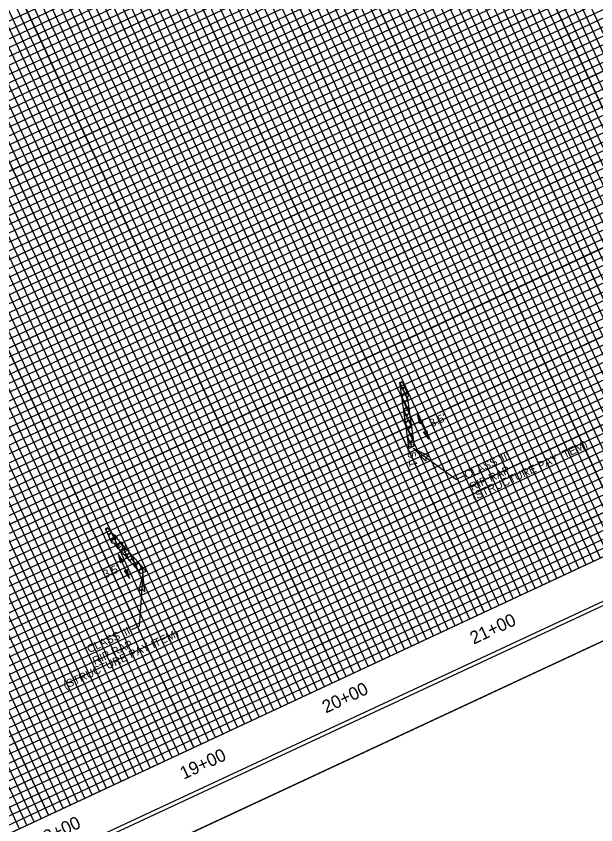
# Model space of a CAD drawing. Extents: x 2320593 to 2322597, y 921119 to 922832.
# Drawn here: x 2321771 to 2322132, y 921501 to 922006 of the extents above; entities that cross this region are included whole.
import ezdxf

# ---------------------------------------------------------------- set-up
doc = ezdxf.new("R2010")
doc.units = 0
for name, color, linetype in [('Default', 7, 'Continuous'), ('Sheet Cutting Line CELL', 7, 'Continuous'), ('Sheet DOT Grid CELL', 7, 'Continuous'), ('Sheet Layout Profile Border Port 2', 7, 'Continuous'), ('Sheet Plan And Profile CELL', 7, 'Continuous'), ('Sheet Plot Border Inside CELL', 7, 'Continuous'), ('Sheet Plot Border Outside CELL', 7, 'Continuous'), ('Sheet Profile Grid Major CELL', 7, 'Continuous'), ('Sheet Profile Grid Middle CELL', 7, 'Continuous'), ('Sheet Profile Grid Minor CELL', 7, 'Continuous')]:
    doc.layers.add(name, color=color, linetype=linetype)

msp = doc.modelspace()

# ---------------------------------------------------------------- linework, layer by layer
at = {"layer": 'Default'}
for p, q in [((2322010.51, 921773.04), (2322011.46, 921773.48)), ((2322011.72, 921764.72), (2322012.58, 921765.12)), ((2322015.98, 921757.82), (2322016.28, 921757.35)), ((2322021.01, 921756.91), (2322028.08, 921741.75)), ((2322012.93, 921756.4), (2322013.7, 921756.76)), ((2322014.15, 921748.09), (2322014.83, 921748.4)), ((2322015.36, 921739.77), (2322015.95, 921740.05)), ((2322019.17, 921737.56), (2322015.9, 921736.03)), ((2322018.23, 921741.11), (2322018.78, 921740.26)), ((2322018.27, 921736.12), (2322045.25, 921716.57)), ((2322049.78, 921718.68), (2322045.25, 921716.57)), ((2321832.76, 921675.5), (2321833.42, 921675.81)), ((2321834.21, 921670.06), (2321841.28, 921654.9)), ((2321838.35, 921669.22), (2321839.1, 921669.57)), ((2321843.94, 921662.95), (2321844.78, 921663.34)), ((2321849.62, 921657.78), (2321847.27, 921624.97)), ((2321848.39, 921657.95), (2321851.66, 921659.47)), ((2321842.74, 921622.86), (2321847.27, 921624.97))]:
    msp.add_line(p, q, dxfattribs=at)
for points in [[(2322015.9, 921736.03), (2322009.9, 921777.19), (2322011.36, 921777.87), (2322013.47, 921773.34)], [(2322012.94, 921774.47), (2322012.51, 921773.97), (2322011.46, 921773.85), (2322010.4, 921776.5), (2322010.97, 921777.69), (2322011.36, 921777.87)], [(2322009.96, 921776.81), (2322010.4, 921776.13), (2322011.32, 921774.16), (2322010.49, 921773.2)], [(2322011.46, 921773.48), (2322012.1, 921772.48), (2322013.02, 921770.51), (2322011.93, 921769.26), (2322011.07, 921769.16)], [(2322014.65, 921770.82), (2322014.21, 921770.32), (2322013.16, 921770.2), (2322012.1, 921772.86), (2322012.67, 921774.04), (2322013.06, 921774.22)], [(2322019.17, 921737.56), (2322014.68, 921768.39), (2322015.58, 921768.81), (2322013.47, 921773.34)], [(2322011.2, 921768.27), (2322011.52, 921767.77), (2322012.44, 921765.8), (2322011.69, 921764.93)], [(2322013.16, 921769.83), (2322013.8, 921768.83), (2322014.72, 921766.86), (2322013.63, 921765.61), (2322012.58, 921765.49), (2322011.53, 921768.15), (2322012.09, 921769.33), (2322013.16, 921769.83)], [(2322014.94, 921766.57), (2322014.86, 921766.56), (2322013.81, 921769.21), (2322014.37, 921770.39), (2322014.76, 921770.58)], [(2322012.58, 921765.12), (2322013.22, 921764.12), (2322014.14, 921762.15), (2322013.06, 921760.9), (2322012.29, 921760.82)], [(2322015.57, 921762.24), (2322015.33, 921761.96), (2322014.29, 921761.85), (2322013.23, 921764.5), (2322013.79, 921765.69), (2322014.86, 921766.18)], [(2322016.16, 921758.22), (2322015.99, 921758.2), (2322014.93, 921760.85), (2322015.49, 921762.04), (2322015.6, 921762.08)], [(2322012.45, 921759.72), (2322012.65, 921759.41), (2322013.57, 921757.44), (2322012.89, 921756.67)], [(2322014.28, 921761.47), (2322014.92, 921760.48), (2322015.84, 921758.5), (2322014.76, 921757.25), (2322013.71, 921757.14), (2322012.65, 921759.79), (2322013.22, 921760.98), (2322014.28, 921761.47)], [(2322016.78, 921753.97), (2322016.46, 921753.61), (2322015.41, 921753.49), (2322014.35, 921756.14), (2322014.92, 921757.33), (2322015.98, 921757.82)], [(2322013.7, 921756.76), (2322014.35, 921755.77), (2322015.27, 921753.79), (2322014.18, 921752.54), (2322013.51, 921752.47)], [(2322015.4, 921753.11), (2322016.05, 921752.12), (2322016.97, 921750.15), (2322015.88, 921748.9), (2322014.83, 921748.78), (2322013.78, 921751.43), (2322014.34, 921752.62), (2322015.4, 921753.11)], [(2322017.38, 921749.87), (2322017.11, 921749.84), (2322016.05, 921752.49), (2322016.62, 921753.68), (2322016.81, 921753.77)], [(2322013.7, 921751.17), (2322013.77, 921751.06), (2322014.69, 921749.09), (2322014.1, 921748.4)], [(2322014.83, 921748.4), (2322015.47, 921747.41), (2322016.39, 921745.44), (2322015.3, 921744.19), (2322014.72, 921744.12)], [(2322017.98, 921745.71), (2322017.58, 921745.25), (2322016.53, 921745.13), (2322015.48, 921747.78), (2322016.04, 921748.97), (2322017.1, 921749.47)], [(2322016.53, 921744.76), (2322017.17, 921743.76), (2322018.09, 921741.79), (2322017.01, 921740.54), (2322015.96, 921740.42), (2322014.9, 921743.07), (2322015.46, 921744.26), (2322016.53, 921744.76)], [(2322014.95, 921742.59), (2322015.81, 921740.73), (2322015.3, 921740.14)], [(2322018.59, 921741.52), (2322018.23, 921741.48), (2322017.18, 921744.13), (2322017.74, 921745.32), (2322018.02, 921745.45)], [(2322015.95, 921740.05), (2322016.6, 921739.05), (2322017.51, 921737.08), (2322017.08, 921736.58)], [(2322017.63, 921736.84), (2322016.6, 921739.42), (2322017.16, 921740.61), (2322018.23, 921741.11)], [(2321851.66, 921659.47), (2321827.64, 921686.44), (2321826.19, 921685.76), (2321828.3, 921681.23)], [(2321839.51, 921673.12), (2321827.64, 921686.44), (2321826.19, 921685.76), (2321828.3, 921681.23)], [(2321829.74, 921684.08), (2321829.88, 921683.78), (2321828.8, 921682.53), (2321827.75, 921682.42), (2321826.69, 921685.07), (2321827.25, 921686.25), (2321827.64, 921686.44)], [(2321848.39, 921657.95), (2321831.32, 921677.12), (2321830.41, 921676.69), (2321828.3, 921681.23)], [(2321830.02, 921683.1), (2321830.66, 921682.11), (2321831.58, 921680.13), (2321830.5, 921678.88), (2321829.45, 921678.77), (2321828.39, 921681.42), (2321828.95, 921682.61), (2321830.02, 921683.1)], [(2321833.09, 921680.32), (2321832.77, 921679.94), (2321831.72, 921679.83), (2321830.67, 921682.48), (2321830.84, 921682.85)], [(2321830.5, 921676.74), (2321830.09, 921677.77), (2321830.65, 921678.96), (2321831.72, 921679.45)], [(2321831.72, 921679.45), (2321832.36, 921678.46), (2321833.28, 921676.49), (2321832.59, 921675.69)], [(2321835.56, 921677.55), (2321835.56, 921677.55), (2321834.47, 921676.3), (2321833.42, 921676.18), (2321832.37, 921678.83), (2321832.93, 921680.02), (2321833.23, 921680.16)], [(2321834.9, 921673.1), (2321834.07, 921675.18), (2321834.63, 921676.37), (2321835.7, 921676.87)], [(2321835.7, 921676.87), (2321836.34, 921675.87), (2321837.26, 921673.9), (2321836.17, 921672.65), (2321835.38, 921672.56)], [(2321838.71, 921674.01), (2321838.45, 921673.71), (2321837.4, 921673.59), (2321836.35, 921676.25), (2321836.48, 921676.52)], [(2321833.42, 921675.81), (2321834.06, 921674.81), (2321834.82, 921673.19)], [(2321835.95, 921671.92), (2321836.33, 921672.72), (2321837.4, 921673.22)], [(2321837.4, 921673.22), (2321838.04, 921672.22), (2321838.96, 921670.25), (2321838.21, 921669.38)], [(2321841.18, 921671.24), (2321840.15, 921670.06), (2321839.1, 921669.95), (2321838.05, 921672.6), (2321838.61, 921673.78), (2321838.82, 921673.88)], [(2321839.1, 921669.57), (2321839.74, 921668.57), (2321840.64, 921666.66)], [(2321840.68, 921666.61), (2321839.75, 921668.95), (2321840.31, 921670.14), (2321841.38, 921670.63)], [(2321841.38, 921670.63), (2321842.02, 921669.64), (2321842.94, 921667.66), (2321841.85, 921666.41), (2321840.94, 921666.31)], [(2321841.58, 921665.59), (2321842.01, 921666.49), (2321843.08, 921666.98)], [(2321844.33, 921667.7), (2321844.13, 921667.48), (2321843.08, 921667.36), (2321842.02, 921670.01), (2321842.11, 921670.19)], [(2321843.08, 921666.98), (2321843.72, 921665.99), (2321844.64, 921664.02), (2321843.82, 921663.08)], [(2321846.79, 921664.94), (2321845.83, 921663.83), (2321844.78, 921663.71), (2321843.72, 921666.36), (2321844.29, 921667.55), (2321844.41, 921667.61)], [(2321844.78, 921663.34), (2321845.42, 921662.34), (2321846.34, 921660.37), (2321846.29, 921660.31)], [(2321846.46, 921660.12), (2321845.42, 921662.71), (2321845.99, 921663.9), (2321847.05, 921664.4)], [(2321847.05, 921664.4), (2321847.7, 921663.4), (2321848.62, 921661.43), (2321847.53, 921660.18), (2321846.51, 921660.07)], [(2321849.94, 921661.4), (2321849.81, 921661.24), (2321848.76, 921661.12), (2321847.7, 921663.78), (2321847.75, 921663.87)], [(2321849.98, 921658.69), (2321849.4, 921660.13), (2321849.97, 921661.31), (2321850, 921661.33)], [(2321847.22, 921659.26), (2321847.69, 921660.25), (2321848.75, 921660.75)], [(2321848.75, 921660.75), (2321849.4, 921659.75), (2321849.91, 921658.66)]]:
    msp.add_lwpolyline(points, dxfattribs=at)
for points in [[(2322022.48, 921751.48), (2322021.01, 921756.91), (2322024.24, 921752.3), (2322023.07, 921752.51)], [(2322026.62, 921747.19), (2322028.08, 921741.75), (2322024.86, 921746.37), (2322026.03, 921746.16)], [(2322026.11, 921728.03), (2322018.27, 921736.12), (2322028.39, 921731.19), (2322026.15, 921730.41)], [(2321837.44, 921665.44), (2321834.21, 921670.06), (2321835.67, 921664.62), (2321836.27, 921665.65)], [(2321838.05, 921659.51), (2321841.28, 921654.9), (2321839.82, 921660.33), (2321839.22, 921659.3)], [(2321850.77, 921646.58), (2321849.62, 921657.78), (2321846.88, 921646.86), (2321848.92, 921648.08)]]:
    msp.add_lwpolyline(points, close=True, dxfattribs=at)
at = {"layer": 'Sheet Cutting Line CELL'}
msp.add_line((2321070.79, 921118.97), (2322596.67, 921830.22), dxfattribs=at)
at = {"layer": 'Sheet DOT Grid CELL'}
for p, q in [((2321022.08, 921617.57), (2322381.64, 922251.29)), ((2321043.21, 921572.25), (2322402.77, 922205.98)), ((2321064.33, 921526.94), (2322423.89, 922160.66)), ((2322043.29, 922148.74), (2322243.97, 921718.22)), ((2321997.97, 922127.62), (2322198.65, 921697.09)), ((2321085.46, 921481.62), (2322445.01, 922115.34)), ((2321952.65, 922106.5), (2322153.33, 921675.97)), ((2321907.33, 922085.37), (2322108.01, 921654.85)), ((2321106.58, 921436.3), (2322466.14, 922070.02)), ((2321862.01, 922064.25), (2322062.69, 921633.72)), ((2321816.69, 922043.12), (2322017.37, 921612.6)), ((2321127.7, 921390.98), (2322487.26, 922024.7)), ((2321771.38, 922022), (2321972.05, 921591.47)), ((2321726.06, 922000.88), (2321926.74, 921570.35)), ((2321148.83, 921345.66), (2322508.39, 921979.38)), ((2321680.74, 921979.75), (2321881.42, 921549.23)), ((2321635.42, 921958.63), (2321836.1, 921528.1)), ((2321169.95, 921300.34), (2322529.51, 921934.06)), ((2321590.1, 921937.5), (2321790.78, 921506.98)), ((2321191.08, 921255.02), (2322550.63, 921888.75))]:
    msp.add_line(p, q, dxfattribs=at)
at = {"layer": 'Sheet Layout Profile Border Port 2'}
msp.add_lwpolyline([(2321046.28, 921684.02), (2322315.2, 922275.49), (2322515.88, 921844.96), (2321246.96, 921253.49)], close=True, dxfattribs=at)
at = {"layer": 'Sheet Plan And Profile CELL'}
msp.add_line((2322561.2, 921866.09), (2321201.64, 921232.36), dxfattribs=at)
msp.add_lwpolyline([(2322128.15, 922795.12), (2320768.59, 922161.4), (2321212.2, 921209.71), (2322571.76, 921843.43)], close=True, dxfattribs=at)
at = {"layer": 'Sheet Plot Border Inside CELL'}
msp.add_lwpolyline([(2321074.13, 921142.59), (2322584.14, 921846.44), (2322138.43, 922802.66), (2320628.41, 922098.81)], close=True, dxfattribs=at)
at = {"layer": 'Sheet Plot Border Outside CELL'}
msp.add_lwpolyline([(2321070.79, 921118.97), (2322596.67, 921830.22), (2322134.06, 922822.69), (2320608.18, 922111.45)], close=True, dxfattribs=at)
at = {"layer": 'Sheet Profile Grid Major CELL'}
for points in [[(2322381.64, 922251.29), (2321022.08, 921617.57), (2321043.21, 921572.25), (2322402.77, 922205.98)], [(2322243.97, 921718.22), (2322043.29, 922148.74), (2322088.61, 922169.87), (2322289.28, 921739.34)], [(2322423.89, 922160.66), (2321064.33, 921526.94), (2321085.46, 921481.62), (2322445.01, 922115.34)], [(2322153.33, 921675.97), (2321952.65, 922106.5), (2321997.97, 922127.62), (2322198.65, 921697.09)], [(2322062.69, 921633.72), (2321862.01, 922064.25), (2321907.33, 922085.37), (2322108.01, 921654.85)], [(2322466.14, 922070.02), (2321106.58, 921436.3), (2321127.7, 921390.98), (2322487.26, 922024.7)], [(2321972.05, 921591.47), (2321771.38, 922022), (2321816.69, 922043.12), (2322017.37, 921612.6)], [(2321881.42, 921549.23), (2321680.74, 921979.75), (2321726.06, 922000.88), (2321926.74, 921570.35)], [(2322508.39, 921979.38), (2321148.83, 921345.66), (2321169.95, 921300.34), (2322529.51, 921934.06)], [(2321790.78, 921506.98), (2321590.1, 921937.5), (2321635.42, 921958.63), (2321836.1, 921528.1)], [(2322550.63, 921888.75), (2321191.08, 921255.02)]]:
    msp.add_lwpolyline(points, dxfattribs=at)
at = {"layer": 'Sheet Profile Grid Middle CELL'}
for p, q in [((2321011.52, 921640.23), (2322371.08, 922273.95)), ((2322392.2, 922228.63), (2321032.65, 921594.91)), ((2321053.77, 921549.6), (2322413.33, 922183.32)), ((2322434.45, 922138), (2321074.89, 921504.28)), ((2321096.02, 921458.96), (2322455.58, 922092.68)), ((2322476.7, 922047.36), (2321117.14, 921413.64)), ((2321138.27, 921368.32), (2322497.82, 922002.04)), ((2322518.95, 921956.72), (2321159.39, 921323)), ((2321180.51, 921277.68), (2322540.07, 921911.4))]:
    msp.add_line(p, q, dxfattribs=at)
for points in [[(2322175.99, 921686.53), (2321975.31, 922117.06), (2322020.63, 922138.18), (2322221.31, 921707.66)], [(2322085.35, 921644.28), (2321884.67, 922074.81), (2321929.99, 922095.93), (2322130.67, 921665.41)], [(2321994.71, 921602.04), (2321794.03, 922032.56), (2321839.35, 922053.69), (2322040.03, 921623.16)], [(2321904.08, 921559.79), (2321703.4, 921990.31), (2321748.72, 922011.44), (2321949.39, 921580.91)], [(2321813.44, 921517.54), (2321612.76, 921948.07), (2321658.08, 921969.19), (2321858.76, 921538.66)]]:
    msp.add_lwpolyline(points, dxfattribs=at)
at = {"layer": 'Sheet Profile Grid Minor CELL'}
for points in [[(2321054.73, 921665.89), (2322323.65, 922257.36), (2322321.54, 922261.89), (2321052.62, 921670.42)], [(2321061.06, 921652.29), (2322329.99, 922243.77), (2322327.87, 922248.3), (2321058.95, 921656.82)], [(2321065.29, 921643.23), (2322334.21, 922234.7), (2322332.1, 922239.23), (2321063.18, 921647.76)], [(2321071.63, 921629.63), (2322340.55, 922221.11), (2322338.44, 922225.64), (2321069.51, 921634.17)], [(2321075.85, 921620.57), (2322344.77, 922212.04), (2322342.66, 922216.57), (2321073.74, 921625.1)], [(2321082.19, 921606.97), (2322351.11, 922198.45), (2322349, 922202.98), (2321080.08, 921611.51)], [(2321086.41, 921597.91), (2322355.33, 922189.38), (2322353.22, 922193.91), (2321084.3, 921602.44)], [(2321090.64, 921588.85), (2322359.56, 922180.32)], [(2321094.86, 921579.78), (2322363.78, 922171.26), (2322361.67, 922175.79), (2321092.75, 921584.31)], [(2321101.2, 921566.19), (2322370.12, 922157.66), (2322365.9, 922166.72), (2321096.98, 921575.25)], [(2322257.56, 921724.55), (2322056.88, 922155.08), (2322061.41, 922157.19), (2322262.09, 921726.67)], [(2321105.43, 921557.12), (2322374.35, 922148.6), (2322372.23, 922153.13), (2321103.31, 921561.66)], [(2322248.5, 921720.33), (2322047.82, 922150.86), (2322052.35, 922152.97), (2322253.03, 921722.44)], [(2322234.9, 921713.99), (2322034.22, 922144.52), (2322038.76, 922146.63), (2322239.43, 921716.11)], [(2321111.76, 921543.53), (2322380.68, 922135), (2322376.46, 922144.06), (2321107.54, 921552.59)], [(2322225.84, 921709.77), (2322025.16, 922140.29), (2322029.69, 922142.41), (2322230.37, 921711.88)], [(2322212.24, 921703.43), (2322011.56, 922133.96), (2322016.1, 922136.07), (2322216.77, 921705.54)], [(2322203.18, 921699.21), (2322002.5, 922129.73), (2322007.03, 922131.85), (2322207.71, 921701.32)], [(2321115.99, 921534.46), (2322384.91, 922125.94), (2322382.8, 922130.47), (2321113.87, 921539)], [(2322189.58, 921692.87), (2321988.9, 922123.4), (2321993.44, 922125.51), (2322194.11, 921694.98)], [(2321122.32, 921520.87), (2322391.25, 922112.34), (2322387.02, 922121.41), (2321118.1, 921529.93)], [(2322180.52, 921688.64), (2321979.84, 922119.17), (2321984.37, 922121.28), (2322185.05, 921690.76)], [(2322157.86, 921678.08), (2321957.18, 922108.61), (2321961.71, 922110.72), (2322162.39, 921680.19)], [(2322166.92, 921682.31), (2321966.25, 922112.83), (2321970.78, 922114.95), (2322171.46, 921684.42)], [(2321126.55, 921511.8), (2322395.47, 922103.28), (2322393.36, 922107.81), (2321124.44, 921516.34)], [(2322144.26, 921671.74), (2321943.59, 922102.27), (2321948.12, 922104.38), (2322148.8, 921673.86)], [(2321132.89, 921498.21), (2322401.81, 922089.68), (2322397.58, 922098.75), (2321128.66, 921507.27)], [(2322135.2, 921667.52), (2321934.52, 922098.05), (2321939.05, 922100.16), (2322139.73, 921669.63)], [(2322121.61, 921661.18), (2321920.93, 922091.71), (2321925.46, 922093.82), (2322126.14, 921663.3)], [(2321137.11, 921489.15), (2322406.03, 922080.62), (2322403.92, 922085.15), (2321135, 921493.68)], [(2322112.54, 921656.96), (2321911.86, 922087.48), (2321916.39, 922089.6), (2322117.07, 921659.07)], [(2322098.95, 921650.62), (2321898.27, 922081.15), (2321902.8, 922083.26), (2322103.48, 921652.73)], [(2321143.45, 921475.55), (2322412.37, 922067.02), (2322408.14, 922076.09), (2321139.22, 921484.61)], [(2322089.88, 921646.4), (2321889.2, 922076.92), (2321893.74, 922079.03), (2322094.41, 921648.51)], [(2322076.29, 921640.06), (2321875.61, 922070.59), (2321880.14, 922072.7), (2322080.82, 921642.17)], [(2322067.22, 921635.83), (2321866.54, 922066.36), (2321871.08, 922068.47), (2322071.75, 921637.95)], [(2321147.67, 921466.49), (2322416.59, 922057.96), (2322414.48, 922062.49), (2321145.56, 921471.02)], [(2322053.63, 921629.5), (2321852.95, 922060.02), (2321857.48, 922062.14), (2322058.16, 921631.61)], [(2322044.56, 921625.27), (2321843.89, 922055.8), (2321848.42, 922057.91), (2322049.1, 921627.38)], [(2321154.01, 921452.89), (2322422.93, 922044.36), (2322418.71, 922053.43), (2321149.79, 921461.95)], [(2322030.97, 921618.93), (2321830.29, 922049.46), (2321834.82, 922051.57), (2322035.5, 921621.05)], [(2322021.9, 921614.71), (2321821.23, 922045.24), (2321825.76, 922047.35), (2322026.44, 921616.82)], [(2321158.24, 921443.83), (2322427.16, 922035.3), (2322425.04, 922039.83), (2321156.12, 921448.36)], [(2322008.31, 921608.37), (2321807.63, 922038.9), (2321812.16, 922041.01), (2322012.84, 921610.49)], [(2321999.24, 921604.15), (2321798.57, 922034.67), (2321803.1, 922036.79), (2322003.78, 921606.26)], [(2321164.57, 921430.23), (2322433.49, 922021.7), (2322429.27, 922030.77), (2321160.35, 921439.3)], [(2321985.65, 921597.81), (2321784.97, 922028.34), (2321789.5, 922030.45), (2321990.18, 921599.92)], [(2321976.59, 921593.59), (2321775.91, 922024.11), (2321780.44, 922026.22), (2321981.12, 921595.7)], [(2321962.99, 921587.25), (2321762.31, 922017.78), (2321766.84, 922019.89), (2321967.52, 921589.36)], [(2321168.8, 921421.17), (2322437.72, 922012.64), (2322435.61, 922017.17), (2321166.68, 921425.7)], [(2321953.93, 921583.02), (2321753.25, 922013.55), (2321757.78, 922015.66), (2321958.46, 921585.14)], [(2321175.13, 921407.57), (2322444.06, 921999.04), (2322439.83, 922008.11), (2321170.91, 921416.64)], [(2321931.27, 921572.46), (2321730.59, 922002.99), (2321735.12, 922005.1), (2321935.8, 921574.57)], [(2321940.33, 921576.69), (2321739.65, 922007.21), (2321744.18, 922009.33), (2321944.86, 921578.8)], [(2321179.36, 921398.51), (2322448.28, 921989.98), (2322446.17, 921994.51), (2321177.25, 921403.04)], [(2321908.61, 921561.9), (2321707.93, 921992.43), (2321712.46, 921994.54), (2321913.14, 921564.01)], [(2321917.67, 921566.12), (2321716.99, 921996.65), (2321721.52, 921998.76), (2321922.2, 921568.24)], [(2321185.7, 921384.91), (2322454.62, 921976.39), (2322450.39, 921985.45), (2321181.47, 921393.98)], [(2321895.01, 921555.56), (2321694.33, 921986.09), (2321698.87, 921988.2), (2321899.54, 921557.67)], [(2321885.95, 921551.34), (2321685.27, 921981.86), (2321689.8, 921983.98), (2321890.48, 921553.45)], [(2321872.35, 921545), (2321671.67, 921975.53), (2321676.21, 921977.64), (2321876.88, 921547.11)], [(2321189.92, 921375.85), (2322458.84, 921967.32), (2322456.73, 921971.85), (2321187.81, 921380.38)], [(2321863.29, 921540.78), (2321662.61, 921971.3), (2321667.14, 921973.41), (2321867.82, 921542.89)], [(2321849.69, 921534.44), (2321649.02, 921964.97), (2321653.55, 921967.08), (2321854.23, 921536.55)], [(2321196.26, 921362.25), (2322465.18, 921953.73), (2322460.95, 921962.79), (2321192.03, 921371.32)], [(2321840.63, 921530.21), (2321639.95, 921960.74), (2321644.48, 921962.85), (2321845.16, 921532.33)], [(2321827.03, 921523.88), (2321626.36, 921954.4), (2321630.89, 921956.52), (2321831.57, 921525.99)], [(2321200.48, 921353.19), (2322469.4, 921944.66), (2322467.29, 921949.19), (2321198.37, 921357.72)], [(2321817.97, 921519.65), (2321617.29, 921950.18), (2321621.82, 921952.29), (2321822.5, 921521.76)], [(2321804.37, 921513.31), (2321603.7, 921943.84), (2321608.23, 921945.95), (2321808.91, 921515.43)], [(2321206.82, 921339.59), (2322475.74, 921931.07), (2322471.52, 921940.13), (2321202.6, 921348.66)], [(2321795.31, 921509.09), (2321594.63, 921939.62), (2321599.16, 921941.73), (2321799.84, 921511.2)], [(2321781.72, 921502.75), (2321581.04, 921933.28), (2321585.57, 921935.39), (2321786.25, 921504.86)], [(2321772.65, 921498.53), (2321571.97, 921929.05), (2321576.51, 921931.17), (2321777.18, 921500.64)], [(2321211.05, 921330.53), (2322479.97, 921922), (2322477.85, 921926.54), (2321208.93, 921335.06)], [(2321217.38, 921316.93), (2322486.3, 921908.41), (2322482.08, 921917.47), (2321213.16, 921326)], [(2321244.84, 921258.02), (2322513.76, 921849.49), (2322511.65, 921854.03), (2321242.73, 921262.55), (2321240.62, 921267.08), (2322509.54, 921858.56), (2322507.43, 921863.09), (2321238.51, 921271.62), (2321236.39, 921276.15), (2321234.28, 921280.68), (2322503.2, 921872.15), (2322501.09, 921876.68), (2321232.17, 921285.21), (2321230.06, 921289.74), (2322498.98, 921881.22), (2322496.87, 921885.75), (2321227.94, 921294.28), (2321225.83, 921298.81), (2321223.72, 921303.34), (2322492.64, 921894.81), (2322490.53, 921899.34), (2321221.61, 921307.87), (2321219.49, 921312.4), (2322488.42, 921903.88)]]:
    msp.add_lwpolyline(points, dxfattribs=at)

# ---------------------------------------------------------------- texts
at = {"layer": 'Default'}
for s, height, rotation, p in [("3.5'", 5, 24.9913, (2322029.9, 921749.12)), ('1.5:1', 5, 278.2921, (2322013.98, 921738.95)), ('(STRUCTURE PAY ITEM)', 5, 24.9913, (2322056.34, 921703.33)), ("CLASS 'II'", 5, 24.9913, (2322051.6, 921716.84)), ('RIP RAP', 5, 24.9913, (2322055.03, 921709.48)), ('1.5:1', 5, 132.7085, (2321841.94, 921671.85)), ("3.5'", 5, 24.9913, (2321826.19, 921654.87)), ('21+00', 8, 24.9913, (2322056.05, 921613.47)), ('(STRUCTURE PAY ITEM)', 5, 24.9913, (2321801.24, 921585.58)), ("CLASS 'II'", 5, 24.9913, (2321816.16, 921608.13)), ('RIP RAP', 5, 24.9913, (2321819.59, 921600.77)), ('20+00', 8, 24.9913, (2321963.82, 921570.48)), ('19+00', 8, 24.9913, (2321875.12, 921529.13)), ('18+00', 8, 24.9913, (2321784.37, 921486.83))]:
    msp.add_text(s, height=height, rotation=rotation, dxfattribs=at).set_placement(p)

doc.saveas('drawing.dxf')
